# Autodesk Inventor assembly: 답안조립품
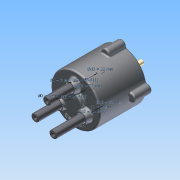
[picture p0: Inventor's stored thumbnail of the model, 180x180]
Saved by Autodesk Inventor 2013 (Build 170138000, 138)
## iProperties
Created: 2014-12
Part Number: 답안조립품
Document SubType Name: Assembly
Designer: WINDOWS7
Mass: 2160.25 g
Surface Area: 1801.19 cm^2
Volume: 438.524 cm^3
Density: 4.92619 g/cm^3
Author: WINDOWS7
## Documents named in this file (14)
- C:\Documents and Settings\Administrator\바탕 화면\Inventor1급\답안조립품.iam
- C:\Documents and Settings\Administrator\바탕 화면\Inventor1급\몸체.ipt
- C:\Documents and Settings\Administrator\바탕 화면\Inventor1급\커버.ipt
- C:\Documents and Settings\Administrator\바탕 화면\Inventor1급\오일실.ipt
- C:\Documents and Settings\Administrator\바탕 화면\Inventor1급\메인 축.ipt
- C:\Documents and Settings\Administrator\바탕 화면\Inventor1급\베어링 NA 4900.ipt
- C:\Documents and Settings\Administrator\바탕 화면\Inventor1급\멈춤링 22 x 1.2.ipt
- C:\Documents and Settings\Administrator\바탕 화면\Inventor1급\멈춤링 10 x 1.ipt
- C:\Documents and Settings\Administrator\바탕 화면\Inventor1급\M5x0.5x20.ipt
- C:\Documents and Settings\Administrator\바탕 화면\Inventor1급\슬라이드 축.ipt
- C:\Documents and Settings\Administrator\바탕 화면\Inventor1급\가변 스프링-01.ipt
- C:\Documents and Settings\Administrator\바탕 화면\Inventor1급\가변 스프링-02.ipt
- C:\Documents and Settings\Administrator\바탕 화면\Inventor1급\가변 스프링-03.ipt
- C:\Documents and Settings\Administrator\바탕 화면\Inventor1급\판캠.ipt
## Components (7 placed, 4 different names)
1. 가변 스프링-01:1
2. 가변 스프링-03:1
3. 가변 스프링-02:1
4. M5x0.5x20:1
5. M5x0.5x20:2
6. M5x0.5x20:3
7. M5x0.5x20:4
